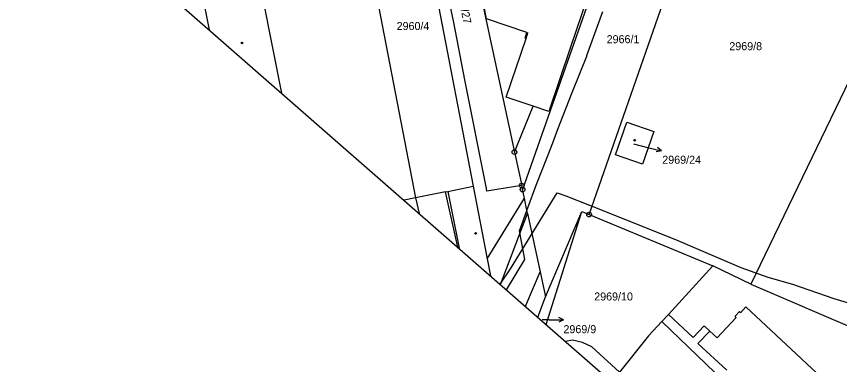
# Model space of a CAD drawing. Extents: x -620475 to -619963, y -1123010 to -1122510.
# Drawn here: x -620474.6 to -620299.9, y -1122840.5 to -1122766.6 of the extents above; entities that cross this region are included whole.
import ezdxf

# ---------------------------------------------------------------- set-up
doc = ezdxf.new("R2010")
doc.units = 0
for name, color, linetype in [('GasNet', 7, 'Continuous'), ('Hranice parcel', 7, 'Continuous'), ('Parcelní čísla', 7, 'Continuous'), ('Pop  PČ popisy', 7, 'Continuous'), ('Rámečky', 7, 'Continuous'), ('Rámečky-tisk', 7, 'Continuous'), ('VAS vodovod', 7, 'Continuous'), ('Vnitřní kresba', 7, 'Continuous'), ('Značky bodu BP', 7, 'Continuous'), ('Značky budov', 7, 'Continuous')]:
    doc.layers.add(name, color=color, linetype=linetype)

msp = doc.modelspace()

# ---------------------------------------------------------------- linework, layer by layer
at = {"layer": 'GasNet'}
for points in [[(-620369.71, -1122820.17), (-620359.82, -1122804.01), (-620357.99, -1122804.64)], [(-620357.99, -1122804.64), (-620352.98, -1122806.61), (-620334.69, -1122813.96)], [(-620334.69, -1122813.96), (-620320.84, -1122819.89), (-620315.13, -1122821.9), (-620309.9, -1122823.43), (-620301.1, -1122826.47)], [(-620371.96, -1122823.41), (-620369.71, -1122820.17)], [(-620301.1, -1122826.47), (-620296.87, -1122827.75), (-620277.93, -1122836.04)]]:
    msp.add_lwpolyline(points, dxfattribs=at)
at = {"layer": 'Hranice parcel'}
for p, q in [((-620392.56, -1122725.51), (-620377.65, -1122802.63)), ((-620404.8, -1122727.88), (-620389.89, -1122805.11)), ((-620284.57, -1122752.56), (-620318.73, -1122823.4)), ((-620353.06, -1122808.63), (-620337.36, -1122763.66)), ((-620368.9, -1122795.38), (-620367.37, -1122802.49)), ((-620383.02, -1122803.72), (-620377.65, -1122802.63)), ((-620377.65, -1122802.63), (-620374.68, -1122818.03)), ((-620367.19, -1122803.33), (-620367.37, -1122802.49)), ((-620383.51, -1122803.82), (-620389.89, -1122805.11)), ((-620383.51, -1122803.82), (-620383.02, -1122803.72)), ((-620366.79, -1122805.17), (-620367.19, -1122803.33)), ((-620389.89, -1122805.11), (-620392.33, -1122805.6)), ((-620374.68, -1122818.03), (-620366.79, -1122805.17)), ((-620362.33, -1122826.09), (-620354.63, -1122807.98)), ((-620362.14, -1122832), (-620354.63, -1122807.98)), ((-620354.63, -1122807.98), (-620353.06, -1122808.63)), ((-620353.06, -1122808.63), (-620326.76, -1122819.51)), ((-620318.73, -1122823.4), (-620326.76, -1122819.51)), ((-620318.73, -1122823.4), (-620280.92, -1122839.64)), ((-620363.95, -1122830.42), (-620362.33, -1122826.09))]:
    msp.add_line(p, q, dxfattribs=at)
for points in [[(-620391.77, -1122717.74), (-620383.57, -1122727.26), (-620368.9, -1122795.38)], [(-620367.37, -1122802.49), (-620372.62, -1122803.29), (-620374.73, -1122803.66), (-620374.83, -1122803.1), (-620379.42, -1122780.06), (-620381.78, -1122767.9), (-620382.73, -1122763.21), (-620385.21, -1122751.08), (-620390.13, -1122725.98), (-620391.77, -1122717.74)], [(-620418.29, -1122782.89), (-620428.27, -1122732.6), (-620440.5, -1122735.14)], [(-620433.66, -1122769.44), (-620440.5, -1122735.14)], [(-620346.26, -1122738.61), (-620349.91, -1122754.18), (-620361.74, -1122787.84), (-620367.19, -1122803.33)], [(-620364.94, -1122785.63), (-620370.66, -1122783.71), (-620366.44, -1122771.24), (-620366.65, -1122771.17), (-620366.25, -1122770.01), (-620374.82, -1122767.12), (-620376.48, -1122758.71), (-620373.99, -1122751.17)], [(-620353.41, -1122750.9), (-620349.8, -1122752.13), (-620352.16, -1122758.92), (-620357, -1122773.13), (-620361.6, -1122786.76), (-620364.94, -1122785.63)], [(-620368.9, -1122795.38), (-620368.33, -1122793.98), (-620364.94, -1122785.63)], [(-620345.02, -1122789.02), (-620339.31, -1122791.01), (-620341.69, -1122797.91), (-620347.42, -1122795.94), (-620345.02, -1122789.02)], [(-620380.95, -1122815.55), (-620383.51, -1122803.82)], [(-620383.02, -1122803.72), (-620380.67, -1122815.79)], [(-620366.1, -1122808.4), (-620366.63, -1122805.92), (-620366.79, -1122805.17)], [(-620371.87, -1122823.49), (-620366.1, -1122808.4)], [(-620366.1, -1122808.4), (-620363.45, -1122820.82), (-620362.33, -1122826.09)], [(-620374.68, -1122818.03), (-620373.98, -1122821.65)], [(-620326.76, -1122819.51), (-620336.22, -1122829.85), (-620337.65, -1122831.34), (-620340.44, -1122834.38), (-620346.62, -1122842.11), (-620352.46, -1122836.69), (-620354.47, -1122835.76), (-620356.61, -1122835.3), (-620358.07, -1122835.57)], [(-620323.82, -1122841.64), (-620329.96, -1122836), (-620327.44, -1122833.35), (-620325.88, -1122834.8), (-620321.83, -1122830.45), (-620322.07, -1122830.23), (-620321.11, -1122829.2), (-620320.88, -1122829.41), (-620319.79, -1122828.24), (-620301.53, -1122845.3)]]:
    msp.add_lwpolyline(points, dxfattribs=at)
at = {"layer": 'Pop  PČ popisy'}
for p, q in [((-620343.66, -1122793.6), (-620340.63, -1122794.37)), ((-620340.63, -1122794.37), (-620337.72, -1122795.1)), ((-620337.72, -1122795.1), (-620338.81, -1122795.34)), ((-620337.72, -1122795.1), (-620338.57, -1122794.37)), ((-620358.5, -1122830.98), (-620359.5, -1122830.48)), ((-620361.5, -1122830.98), (-620363.03, -1122830.98)), ((-620361.5, -1122830.98), (-620358.5, -1122830.98)), ((-620358.5, -1122830.98), (-620359.5, -1122831.48))]:
    msp.add_line(p, q, dxfattribs=at)
at = {"layer": 'Rámečky'}
msp.add_lwpolyline([(-620279.07, -1122510.07), (-620474.61, -1122733.62), (-620158.49, -1123010.14)], dxfattribs=at)
at = {"layer": 'Rámečky-tisk'}
msp.add_lwpolyline([(-620279.07, -1122510.07), (-620474.61, -1122733.62), (-620158.49, -1123010.14)], dxfattribs=at)
at = {"layer": 'VAS vodovod'}
for points in [[(-620367.84, -1122812.07), (-620366.06, -1122807.23), (-620364.28, -1122802.38), (-620361.9, -1122796.29), (-620360.79, -1122793.4), (-620359.67, -1122790.51), (-620356.62, -1122782.75), (-620353.57, -1122775), (-620353.53, -1122774.89), (-620350.12, -1122765.53)], [(-620370.56, -1122824.63), (-620366.7, -1122818.15), (-620367.27, -1122815.11), (-620367.84, -1122812.07)]]:
    msp.add_lwpolyline(points, dxfattribs=at)
at = {"layer": 'Vnitřní kresba'}
for p, q in [((-620366.44, -1122771.24), (-620366.05, -1122770.08)), ((-620366.25, -1122770.01), (-620366.05, -1122770.08)), ((-620389.89, -1122805.11), (-620389.13, -1122808.4)), ((-620366.52, -1122827.92), (-620363.45, -1122820.82)), ((-620366.59, -1122828.11), (-620366.52, -1122827.92)), ((-620366.52, -1122827.92), (-620366.59, -1122828.11)), ((-620330.98, -1122834.72), (-620336.22, -1122829.85)), ((-620337.65, -1122831.34), (-620326.36, -1122842.19)), ((-620328.61, -1122832.23), (-620330.98, -1122834.72)), ((-620327.44, -1122833.35), (-620328.61, -1122832.23))]:
    msp.add_line(p, q, dxfattribs=at)
at = {"layer": 'Značky bodu BP'}
for centre, radius in [((-620368.9, -1122795.38), 0.5), ((-620368.9, -1122795.38), 0.0303), ((-620367.37, -1122802.49), 0.5), ((-620367.37, -1122802.49), 0.0303), ((-620367.19, -1122803.33), 0.5), ((-620367.19, -1122803.33), 0.0303), ((-620353.06, -1122808.63), 0.5), ((-620353.06, -1122808.63), 0.0303)]:
    msp.add_circle(centre, radius, dxfattribs=at)
at = {"layer": 'Značky budov'}
for centre in [(-620426.75, -1122772.22), (-620343.38, -1122792.85), (-620377.15, -1122812.63)]:
    msp.add_circle(centre, 0.175, dxfattribs=at)

# ---------------------------------------------------------------- texts
at = {"layer": 'Parcelní čísla'}
msp.add_text('2960/27', height=1.7, rotation=282, dxfattribs=at).set_placement((-620381.37, -1122760.25))
for s, p in [('2960/4', (-620393.91, -1122769.47)), ('2966/1', (-620349.33, -1122772.27)), ('2969/8', (-620323.29, -1122773.75)), ('2969/24', (-620337.52, -1122797.85)), ('2969/10', (-620351.97, -1122826.87)), ('2969/9', (-620358.5, -1122833.81))]:
    msp.add_text(s, height=1.7, dxfattribs=at).set_placement(p)

doc.saveas('drawing.dxf')
